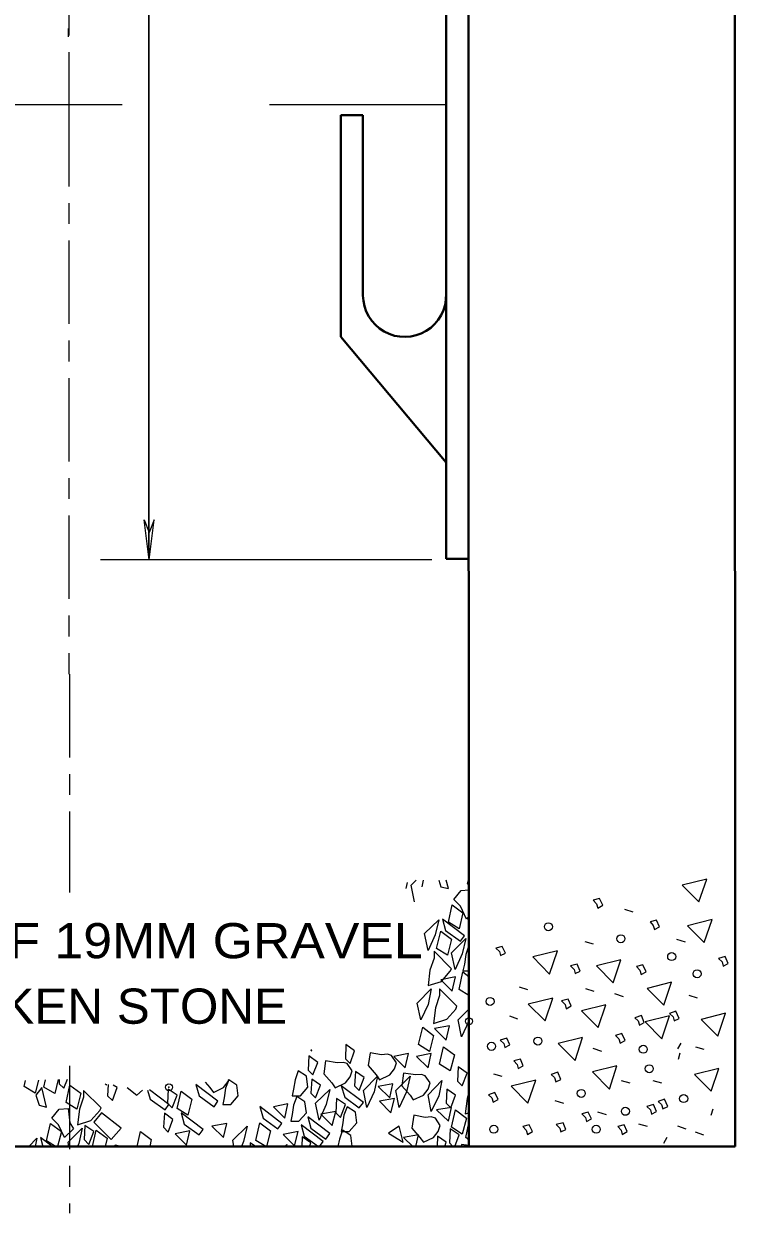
# Model space of a CAD drawing. Extents: x 312583 to 312854, y 144419 to 144597.
# Drawn here: x 312722.29 to 312737.65, y 144469.78 to 144495.47 of the extents above; entities that cross this region are included whole.
import ezdxf

# ---------------------------------------------------------------- set-up
doc = ezdxf.new("R2010")
doc.units = 0
doc.header["$LTSCALE"] = 0.3
doc.header["$PDMODE"] = 32
doc.header["$PDSIZE"] = 0.15
doc.linetypes.add('LONG_DASH_SHORT_DASH', pattern=[9.9, 6, -1.2, 1.5, -1.2])
doc.layers.add('1', color=7, linetype='Continuous', lineweight=40)
doc.layers.add('2', color=7, linetype='Continuous', lineweight=13)

msp = doc.modelspace()

# ---------------------------------------------------------------- linework, layer by layer
at = {"layer": '1'}
for p, q in [((312737.6342, 144516.7375), (312737.6495, 144471.2205)), ((312731.8842, 144515.7792), (312731.8995, 144471.2205)), ((312731.4088, 144515.4265), (312731.4088, 144483.9165)), ((312729.1318, 144493.4999), (312729.1318, 144488.7082)), ((312729.6072, 144493.4999), (312729.1318, 144493.4999)), ((312729.6072, 144493.4999), (312729.6072, 144489.6052)), ((312731.4088, 144485.9942), (312729.1318, 144488.7082)), ((312731.4088, 144483.9165), (312731.8842, 144483.9165))]:
    msp.add_line(p, q, dxfattribs=at)
at = {"layer": '1', "lineweight": 13}
for p, q in [((312724.9842, 144512.5975), (312724.9842, 144483.8935)), ((312724.9842, 144483.9779), (312724.9842, 144512.5975))]:
    msp.add_line(p, q, dxfattribs=at)
at = {"layer": '1', "linetype": 'LONG_DASH_SHORT_DASH', "lineweight": 13}
for p, q in [((312723.2592, 144503.7732), (312723.2592, 144493.7605)), ((312723.2438, 144495.3705), (312723.2438, 144495.1942)), ((312723.2592, 144493.7605), (312723.2592, 144481.4249)), ((312723.2745, 144481.4249), (312723.2745, 144476.7099)), ((312723.2745, 144472.9609), (312723.2745, 144469.7792)), ((312723.2745, 144472.6772), (312723.2745, 144471.2205))]:
    msp.add_line(p, q, dxfattribs=at)
at = {"layer": '1'}
msp.add_lwpolyline([(312708.8995, 144471.2205), (312716.2748, 144471.2205), (312737.6495, 144471.2205)], dxfattribs=at)
msp.add_arc((312730.509, 144489.6076), 0.8984, 180.03057, 1.87136, dxfattribs=at)
at = {"layer": '2'}
for p, q in [((312724.4092, 144493.7222), (312719.8475, 144493.7222)), ((312731.4088, 144493.7222), (312727.5908, 144493.7222)), ((312724.8845, 144484.7599), (312724.9918, 144484.4839)), ((312724.9918, 144483.8935), (312724.8845, 144484.7599)), ((312725.0992, 144484.7599), (312724.9918, 144484.4839)), ((312724.9918, 144483.8935), (312725.0992, 144484.7599)), ((312731.0945, 144483.8935), (312723.9415, 144483.8935)), ((312730.5655, 144476.9245), (312730.5348, 144476.7942)), ((312730.6498, 144476.8632), (312730.7572, 144476.9705)), ((312730.7265, 144476.5029), (312730.6498, 144476.8632)), ((312730.9105, 144476.9705), (312730.8798, 144476.8325)), ((312731.8688, 144476.8939), (312731.8918, 144476.9705)), ((312731.8995, 144476.8709), (312731.8688, 144476.8939)), ((312735.4492, 144476.2805), (312735.2652, 144476.3419)), ((312731.8995, 144476.1962), (312731.8458, 144476.1349)), ((312734.5905, 144475.5905), (312734.4065, 144475.6442)), ((312736.5762, 144475.6365), (312736.3922, 144475.6902)), ((312731.8995, 144474.4789), (312731.6848, 144474.6092)), ((312733.1722, 144474.6015), (312732.9882, 144474.6629)), ((312734.6058, 144474.5709), (312734.4218, 144474.6245)), ((312735.2345, 144474.4559), (312735.0505, 144474.5172)), ((312736.8368, 144474.4252), (312736.6528, 144474.4789)), ((312731.6695, 144473.9575), (312731.8995, 144474.1875)), ((312731.8995, 144473.9345), (312731.8765, 144473.8962)), ((312731.8765, 144473.8962), (312731.8995, 144473.8119)), ((312732.9575, 144473.9729), (312732.7812, 144474.0342)), ((312736.4765, 144473.4515), (312736.3998, 144473.3289)), ((312734.7668, 144473.2752), (312734.5828, 144473.3365)), ((312736.4535, 144473.2369), (312736.4152, 144473.0989)), ((312736.9825, 144473.3135), (312736.7985, 144473.3672)), ((312722.2932, 144472.5162), (312722.3238, 144472.6465)), ((312722.7148, 144472.5009), (312722.7532, 144472.6619)), ((312732.6202, 144472.7309), (312732.4362, 144472.7845)), ((312735.3802, 144472.5852), (312735.1962, 144472.6389)), ((312736.0625, 144472.5852), (312735.8785, 144472.6389)), ((312724.9535, 144472.4395), (312725.0148, 144472.2402)), ((312726.2032, 144472.6082), (312726.3028, 144472.4932)), ((312733.9465, 144472.1482), (312733.7625, 144472.2095)), ((312734.8665, 144471.9029), (312734.6825, 144471.9642)), ((312737.1665, 144472.0255), (312737.1205, 144471.8875)), ((312731.8305, 144471.4122), (312731.8995, 144471.7265)), ((312735.7558, 144471.6499), (312735.5718, 144471.7035)), ((312736.5915, 144471.5962), (312736.4075, 144471.6575)), ((312722.9678, 144471.2205), (312722.7762, 144471.3432)), ((312726.8242, 144471.2205), (312726.8012, 144471.3585)), ((312727.5142, 144471.2205), (312727.2995, 144471.3509)), ((312728.2962, 144471.4275), (312728.2885, 144471.2205)), ((312728.3422, 144471.4429), (312728.6488, 144471.2205)), ((312730.4888, 144471.4122), (312730.6882, 144471.2205)), ((312731.2172, 144471.4429), (312731.2095, 144471.2205)), ((312731.8995, 144471.3662), (312731.8305, 144471.4122)), ((312736.1698, 144471.4122), (312736.1008, 144471.2819)), ((312736.9748, 144471.4659), (312736.7908, 144471.5272)), ((312723.2592, 144471.2205), (312723.2438, 144471.3125)), ((312724.2558, 144471.2512), (312724.2405, 144471.2205)), ((312724.3938, 144471.2205), (312724.2558, 144471.2512)), ((312727.1768, 144471.2972), (312727.1768, 144471.2205)), ((312727.2918, 144471.2205), (312727.1768, 144471.2972))]:
    msp.add_line(p, q, dxfattribs=at)
for points in [[(312736.5072, 144476.8632), (312736.8675, 144476.5029), (312737.0362, 144476.9935)], [(312734.6518, 144476.4645), (312734.6825, 144476.3725), (312734.7898, 144476.4339), (312734.7208, 144476.5795), (312734.5828, 144476.5412)], [(312731.4548, 144476.0659), (312731.5392, 144476.4415), (312731.7692, 144476.2652), (312731.6848, 144475.9202)], [(312730.9412, 144475.8205), (312731.2478, 144476.1195), (312731.1712, 144475.7899), (312731.0178, 144475.4525)], [(312731.3935, 144475.8895), (312731.7155, 144475.6595), (312731.7998, 144475.7745), (312731.3245, 144476.1349)], [(312735.8785, 144475.9969), (312735.9092, 144475.9049), (312736.0165, 144475.9662), (312735.9475, 144476.1119), (312735.8095, 144476.0735)], [(312736.6222, 144475.9892), (312736.9825, 144475.6289), (312737.1512, 144476.1272)], [(312731.2018, 144475.4985), (312731.2938, 144475.8742), (312731.5238, 144475.6979), (312731.4395, 144475.3529)], [(312731.5238, 144475.4065), (312731.8305, 144475.7132), (312731.7538, 144475.3835), (312731.6005, 144475.0462)], [(312731.1482, 144475.2915), (312731.0562, 144475.0309), (312731.0178, 144474.7012), (312731.3092, 144474.7855), (312731.4932, 144475.0079), (312731.5238, 144475.0615), (312731.1482, 144475.4372)], [(312732.5588, 144475.4295), (312732.5818, 144475.3452), (312732.6892, 144475.3989), (312732.6202, 144475.5445), (312732.4822, 144475.5062)], [(312733.2795, 144475.3145), (312733.6398, 144474.9465), (312733.8085, 144475.4449)], [(312734.6518, 144475.1229), (312735.0122, 144474.7549), (312735.1808, 144475.2532)], [(312737.3658, 144475.2072), (312737.3888, 144475.1152), (312737.4962, 144475.1765), (312737.4348, 144475.3222), (312737.2892, 144475.2839)], [(312734.1688, 144475.0462), (312734.1918, 144474.9542), (312734.2992, 144475.0079), (312734.2378, 144475.1612), (312734.0922, 144475.1229)], [(312735.5872, 144475.0309), (312735.6178, 144474.9389), (312735.7252, 144474.9925), (312735.6562, 144475.1459), (312735.5182, 144475.1075)], [(312731.2938, 144474.8239), (312731.5392, 144474.5785), (312731.6082, 144474.8852)], [(312735.7482, 144474.6322), (312736.1085, 144474.2719), (312736.2772, 144474.7702)], [(312730.7802, 144474.3179), (312731.0868, 144474.6245), (312731.0178, 144474.2872), (312730.8568, 144473.9575)], [(312731.2632, 144474.4789), (312731.1788, 144474.2182), (312731.1328, 144473.8809), (312731.4242, 144473.9729), (312731.6158, 144474.1875), (312731.6388, 144474.2489), (312731.2632, 144474.6245)], [(312733.1798, 144474.2949), (312733.5478, 144473.9345), (312733.7088, 144474.4252)], [(312733.9772, 144474.2872), (312734.0002, 144474.1952), (312734.1075, 144474.2565), (312734.0385, 144474.4022), (312733.9005, 144474.3639)], [(312734.3298, 144474.1492), (312734.6902, 144473.7889), (312734.8588, 144474.2795)], [(312735.5565, 144473.9345), (312735.5795, 144473.8425), (312735.6868, 144473.8962), (312735.6255, 144474.0495), (312735.4798, 144474.0035)], [(312735.7022, 144473.9115), (312736.0625, 144473.5435), (312736.2312, 144474.0419)], [(312736.3078, 144474.0189), (312736.3308, 144473.9345), (312736.4382, 144473.9882), (312736.3692, 144474.1415), (312736.2312, 144474.0955)], [(312736.9135, 144473.9652), (312737.2738, 144473.6049), (312737.4425, 144474.1032)], [(312730.8108, 144473.4209), (312730.9028, 144473.7965), (312731.1328, 144473.6202), (312731.0485, 144473.2752)], [(312731.1558, 144473.7659), (312731.4088, 144473.5205), (312731.4778, 144473.8272)], [(312735.1348, 144473.5435), (312735.1655, 144473.4515), (312735.2728, 144473.5129), (312735.2038, 144473.6585), (312735.0658, 144473.6202)], [(312729.2392, 144473.4209), (312729.2315, 144473.1142), (312729.3312, 144473.0145), (312729.4308, 144473.2905)], [(312732.6508, 144473.4439), (312732.6738, 144473.3595), (312732.7812, 144473.4132), (312732.7198, 144473.5589), (312732.5742, 144473.5205)], [(312733.8238, 144473.4439), (312734.1918, 144473.0759), (312734.3528, 144473.5742)], [(312728.4418, 144473.1755), (312728.4265, 144472.8689), (312728.5262, 144472.7692), (312728.6335, 144473.0375)], [(312729.8985, 144472.7692), (312729.9675, 144472.6619), (312730.1898, 144472.7692), (312730.2895, 144472.8995), (312730.3355, 144473.0299), (312730.2282, 144473.1832), (312730.1438, 144473.2139), (312730.0135, 144473.1985), (312729.7682, 144473.2445), (312729.7222, 144472.9685)], [(312730.2742, 144473.1679), (312730.5195, 144472.9225), (312730.5962, 144473.2292)], [(312730.7648, 144473.1679), (312731.0178, 144472.9225), (312731.0868, 144473.2292)], [(312731.2632, 144472.9992), (312731.3475, 144473.3749), (312731.5852, 144473.1985), (312731.4932, 144472.8535)], [(312728.9402, 144472.5929), (312729.0092, 144472.4855), (312729.2315, 144472.5929), (312729.3312, 144472.7232), (312729.3772, 144472.8535), (312729.2698, 144473.0145), (312729.1855, 144473.0375), (312729.0552, 144473.0299), (312728.8022, 144473.0682), (312728.7638, 144472.7922)], [(312731.6695, 144472.9379), (312731.6542, 144472.6312), (312731.7538, 144472.5315), (312731.8612, 144472.8075)], [(312732.9422, 144472.9915), (312732.9652, 144472.9072), (312733.0725, 144472.9609), (312733.0112, 144473.1065), (312732.8655, 144473.0682)], [(312734.5675, 144472.8305), (312734.9355, 144472.4625), (312735.0965, 144472.9609)], [(312736.7678, 144472.7769), (312737.1282, 144472.4165), (312737.2968, 144472.9072)], [(312726.7168, 144472.6619), (312726.6402, 144472.4779), (312726.6095, 144472.2709), (312726.5865, 144472.1252), (312726.7552, 144472.1252), (312726.9162, 144472.3169), (312726.8855, 144472.5469)], [(312728.2118, 144472.8535), (312728.1428, 144472.6619), (312728.1122, 144472.4625), (312728.0815, 144472.3169), (312728.2578, 144472.3169), (312728.4188, 144472.5009), (312728.3882, 144472.7385)], [(312728.5032, 144472.6772), (312728.4878, 144472.3705), (312728.5875, 144472.2709), (312728.6948, 144472.5469)], [(312729.4462, 144472.8382), (312729.4308, 144472.5315), (312729.5305, 144472.4319), (312729.6378, 144472.7079)], [(312729.6225, 144472.4319), (312729.9215, 144472.7385), (312729.8525, 144472.4012), (312729.6915, 144472.0639)], [(312730.3202, 144472.4319), (312730.6268, 144472.7385), (312730.5502, 144472.4012), (312730.3892, 144472.0639)], [(312730.6268, 144472.3322), (312730.6958, 144472.2249), (312730.9182, 144472.3322), (312731.0178, 144472.4625), (312731.0638, 144472.5929), (312730.9565, 144472.7462), (312730.8722, 144472.7769), (312730.7418, 144472.7692), (312730.4888, 144472.8075), (312730.4505, 144472.5315)], [(312731.0178, 144472.3399), (312731.3168, 144472.6465), (312731.2478, 144472.3169), (312731.0868, 144471.9795)], [(312732.8118, 144472.5239), (312733.1722, 144472.1559), (312733.3408, 144472.6542)], [(312733.7472, 144472.7079), (312733.7778, 144472.6159), (312733.8852, 144472.6695), (312733.8162, 144472.8229), (312733.6782, 144472.7769)], [(312722.5462, 144472.3322), (312722.6152, 144472.1099), (312722.7762, 144472.0715), (312722.6765, 144472.4932)], [(312723.1978, 144472.1712), (312723.2822, 144472.5469), (312723.5198, 144472.3705), (312723.4278, 144472.0255)], [(312723.5735, 144472.2862), (312723.4892, 144472.0255), (312723.4432, 144471.6882), (312723.7345, 144471.7802), (312723.9262, 144471.9949), (312723.9568, 144472.0562), (312723.5735, 144472.4319)], [(312725.4058, 144472.4625), (312725.3905, 144472.1559), (312725.4902, 144472.0562), (312725.5975, 144472.3322)], [(312725.5975, 144472.0409), (312725.6818, 144472.4165), (312725.9118, 144472.2402), (312725.8275, 144471.8952)], [(312726.0728, 144472.3169), (312726.3948, 144472.0792), (312726.4792, 144472.2019), (312726.0038, 144472.5622)], [(312728.5875, 144472.1559), (312728.8942, 144472.4549), (312728.8175, 144472.1252), (312728.6642, 144471.7879)], [(312729.2162, 144472.2862), (312729.5305, 144472.0562), (312729.6225, 144472.1712), (312729.1395, 144472.5315)], [(312729.9368, 144472.5162), (312730.1898, 144472.2709), (312730.2588, 144472.5775)], [(312731.4242, 144472.4625), (312731.4088, 144472.1559), (312731.5085, 144472.0562), (312731.6082, 144472.3322)], [(312732.3902, 144472.2709), (312732.4208, 144472.1789), (312732.5282, 144472.2325), (312732.4592, 144472.3859), (312732.3212, 144472.3399)], [(312727.6752, 144472.0792), (312727.9205, 144471.8339), (312727.9895, 144472.1405)], [(312728.1812, 144472.3015), (312728.1122, 144472.1099), (312728.0815, 144471.9105), (312728.0508, 144471.7649), (312728.2272, 144471.7649), (312728.3882, 144471.9489), (312728.3575, 144472.1865)], [(312729.0398, 144472.2555), (312729.0245, 144471.9489), (312729.1242, 144471.8492), (312729.2315, 144472.1252)], [(312729.9675, 144472.2019), (312730.2128, 144471.9489), (312730.2895, 144472.2555)], [(312735.8172, 144472.0102), (312735.8402, 144471.9182), (312735.9475, 144471.9795), (312735.8862, 144472.1252), (312735.7405, 144472.0869)], [(312736.0548, 144472.1252), (312736.0855, 144472.0332), (312736.1928, 144472.0869), (312736.1238, 144472.2402), (312735.9858, 144472.1942)], [(312723.1672, 144471.4122), (312723.0368, 144471.6882), (312722.8912, 144471.8339), (312723.0522, 144472.0255), (312723.2438, 144472.0409), (312723.2822, 144471.7342), (312723.3588, 144471.6039)], [(312723.9645, 144471.9489), (312723.7958, 144471.7495), (312724.1715, 144471.3739), (312724.3862, 144471.6192)], [(312725.3215, 144471.9412), (312725.3062, 144471.6345), (312725.4058, 144471.5272), (312725.5055, 144471.8032)], [(312725.7508, 144471.7035), (312726.0728, 144471.4735), (312726.1572, 144471.5885), (312725.6818, 144471.9489)], [(312727.4528, 144471.8339), (312727.7748, 144471.6039), (312727.8592, 144471.7189), (312727.3838, 144472.0869)], [(312728.4878, 144471.6192), (312728.8098, 144471.3815), (312728.8942, 144471.5042), (312728.4188, 144471.8645)], [(312728.7025, 144471.9182), (312728.9478, 144471.6729), (312729.0245, 144471.9795)], [(312729.2698, 144472.0792), (312729.2008, 144471.8952), (312729.1702, 144471.6882), (312729.1395, 144471.5425), (312729.3158, 144471.5425), (312729.4768, 144471.7342), (312729.4462, 144471.9642)], [(312730.8415, 144471.4122), (312730.9182, 144471.3125), (312731.1328, 144471.4122), (312731.2325, 144471.5425), (312731.2785, 144471.6729), (312731.1788, 144471.8339), (312731.0868, 144471.8645), (312730.9565, 144471.8492), (312730.7112, 144471.8952), (312730.6652, 144471.6192)], [(312731.2018, 144472.0102), (312731.4548, 144471.7649), (312731.5238, 144472.0639)], [(312731.5238, 144471.6345), (312731.6082, 144472.0102), (312731.8458, 144471.8339), (312731.7538, 144471.4889)], [(312734.4142, 144471.8492), (312734.4372, 144471.7572), (312734.5445, 144471.8185), (312734.4755, 144471.9642), (312734.3375, 144471.9259)], [(312723.6042, 144471.6729), (312723.5888, 144471.3739), (312723.6885, 144471.2665), (312723.7958, 144471.5425)], [(312726.3488, 144471.6575), (312726.6018, 144471.4122), (312726.6708, 144471.7189)], [(312730.1592, 144471.5119), (312730.4812, 144471.3125), (312730.3892, 144471.6575)], [(312733.1338, 144471.5732), (312733.1645, 144471.4812), (312733.2718, 144471.5425), (312733.2028, 144471.6882), (312733.0648, 144471.6499)], [(312733.8622, 144471.6192), (312733.8852, 144471.5349), (312733.9925, 144471.5885), (312733.9312, 144471.7342), (312733.7855, 144471.6959)], [(312735.1885, 144471.5732), (312735.2115, 144471.4812), (312735.3188, 144471.5425), (312735.2498, 144471.6882), (312735.1118, 144471.6499)], [(312725.5515, 144471.4965), (312725.7968, 144471.2512), (312725.8735, 144471.5579)], [(312727.8898, 144471.4812), (312728.1352, 144471.2359), (312728.2118, 144471.5425)]]:
    msp.add_lwpolyline(points, close=True, dxfattribs=at)
for points in [[(312731.2478, 144476.9705), (312731.2938, 144476.8325), (312731.4548, 144476.7942), (312731.4088, 144476.9705)], [(312731.8458, 144476.1349), (312731.7155, 144476.4109), (312731.5698, 144476.5565), (312731.7308, 144476.7482), (312731.8995, 144476.7635)], [(312731.8995, 144475.5599), (312731.8305, 144475.3682), (312731.7998, 144475.1612), (312731.7692, 144475.0155), (312731.8995, 144475.0155)], [(312731.6848, 144474.6092), (312731.7692, 144474.9925), (312731.8995, 144474.8929)], [(312731.8995, 144473.9269), (312731.7385, 144473.5895), (312731.6695, 144473.9575)], [(312728.4802, 144473.2982), (312728.5032, 144473.2905), (312728.4955, 144473.3135)], [(312722.5998, 144472.6542), (312722.5308, 144472.3705), (312722.2932, 144472.5162)], [(312723.0292, 144472.6695), (312722.9525, 144472.3629), (312722.7148, 144472.5009)], [(312723.0522, 144472.6695), (312723.0522, 144472.5775), (312723.1518, 144472.4779), (312723.2285, 144472.6772)], [(312726.3028, 144472.4932), (312726.3795, 144472.3859), (312726.6018, 144472.4932), (312726.7015, 144472.6235), (312726.7168, 144472.6772)], [(312724.0412, 144472.5775), (312724.0718, 144472.5469), (312724.0718, 144472.5699)], [(312724.1102, 144472.5622), (312724.0948, 144472.3169), (312724.2022, 144472.2172), (312724.3018, 144472.4932), (312724.2175, 144472.5469)], [(312724.5165, 144472.4932), (312724.7235, 144472.3322), (312724.8462, 144472.4395)], [(312725.0148, 144472.2402), (312725.3368, 144472.0102), (312725.4212, 144472.1252), (312724.9995, 144472.4472)], [(312731.8995, 144472.3859), (312731.8612, 144472.2555), (312731.8152, 144471.9259), (312731.8995, 144471.9489)], [(312722.7762, 144471.3432), (312722.8605, 144471.7189), (312723.0982, 144471.5425), (312723.0138, 144471.2205)], [(312723.2438, 144471.3125), (312723.5428, 144471.6192), (312723.4738, 144471.2819), (312723.4432, 144471.2205)], [(312726.8012, 144471.3585), (312727.1078, 144471.6575), (312727.0312, 144471.3279), (312726.9852, 144471.2205)], [(312727.2995, 144471.3509), (312727.3838, 144471.7342), (312727.6138, 144471.5579), (312727.5295, 144471.2205)], [(312728.6718, 144471.2205), (312728.7485, 144471.3279), (312728.2732, 144471.6882), (312728.3422, 144471.4429)], [(312731.4932, 144471.6039), (312731.4778, 144471.2972), (312731.5545, 144471.2205)], [(312731.5928, 144471.2205), (312731.6848, 144471.4735), (312731.4932, 144471.6039)], [(312722.3928, 144471.2205), (312722.5692, 144471.3969), (312722.5308, 144471.2205)], [(312722.8988, 144471.2205), (312722.6458, 144471.4122), (312722.6995, 144471.2205)], [(312723.7728, 144471.2205), (312723.8495, 144471.5732), (312724.0872, 144471.3969), (312724.0412, 144471.2205)], [(312724.7312, 144471.2205), (312724.8078, 144471.5425), (312725.0378, 144471.3739), (312725.0072, 144471.2205)], [(312728.4572, 144471.2205), (312728.4878, 144471.2972), (312728.2962, 144471.4275)], [(312729.1702, 144471.5732), (312729.1012, 144471.3815), (312729.0705, 144471.2205)], [(312729.3695, 144471.2205), (312729.3772, 144471.2282), (312729.3465, 144471.4582), (312729.1702, 144471.5732)], [(312730.7495, 144471.2205), (312730.8108, 144471.4735), (312730.4888, 144471.4122)], [(312731.3782, 144471.2205), (312731.4088, 144471.3125), (312731.2172, 144471.4429)], [(312727.9205, 144471.2205), (312727.9665, 144471.2665), (312727.9512, 144471.2205)], [(312731.8995, 144471.2435), (312731.7385, 144471.2665), (312731.7308, 144471.2205)]]:
    msp.add_lwpolyline(points, dxfattribs=at)
for centre in [(312733.6145, 144475.968), (312735.1805, 144475.7092), (312736.2778, 144475.322), (312736.8269, 144474.9512), (312732.3553, 144474.3532), (312732.3869, 144473.3843), (312733.3884, 144473.4974), (312735.6644, 144473.3201), (312735.7938, 144472.9003), (312734.3247, 144472.3675), (312736.5365, 144472.2544), (312735.2773, 144471.9803), (312732.4358, 144471.5922), (312734.6476, 144471.5922)]:
    msp.add_circle(centre, 0.0865, dxfattribs=at)
for p in [(312731.8995, 144473.9269), (312725.4212, 144472.5009)]:
    msp.add_point(p, dxfattribs=at)

# ---------------------------------------------------------------- texts
for s, width, p in [('150MM OF 19MM GRAVEL ', 1.1, (312717.0467, 144475.2866)), ('OR BROKEN STONE', 1.05, (312717.5935, 144473.8722))]:
    msp.add_text(s, height=0.76, dxfattribs=dict(at, width=width)).set_placement(p)

doc.saveas('drawing.dxf')
